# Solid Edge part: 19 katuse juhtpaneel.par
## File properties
Author: Henri
Template: Normal.par
Last saved by: Henri
Revision: 8
Application: Solid Edge
Accuracy: 0,990
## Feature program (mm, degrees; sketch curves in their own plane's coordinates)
sketch for "unnamed Protrusion 1" plane through (0, 0, 0) normal (0, 0, 1) x-axis (1, 0, 0)
  line (-20, -175) -> (-20, 175)
  line (-20, 175) -> (20, 175)
  line (20, 175) -> (20, -175)
  line (20, -175) -> (-20, -175)
extrude "unnamed Protrusion 1" add finite 40 along +normal
sketch for "ExtrudedProtrusion_2" plane through (0, 0, 0) normal (0, 0, 1) x-axis (1, 0, 0)
  line (-95, 62.5) -> (-20, 62.5)
  line (-20, 62.5) -> (-20, 112.5)
  line (-20, 112.5) -> (-95, 112.5)
  line (-95, 112.5) -> (-95, 62.5)
extrude "ExtrudedProtrusion_2" add finite 2.5 along +normal
sketch for "ExtrudedProtrusion_3" plane through (0, 0, 0) normal (0, 0, 1) x-axis (1, 0, 0)
  line (-35, 77.5) -> (-15, 77.5)
  line (-15, 97.5) -> (-15, 77.5)
  line (-35, 97.5) -> (-15, 97.5)
  line (-35, 97.5) -> (-35, 77.5)
extrude "ExtrudedProtrusion_3" add finite 60 along +normal
sketch for "ExtrudedProtrusion_4" plane through (-35, 87.5, 31.25) normal (-1, 0, 0) x-axis (0, -1, 0)
  circle centre (0, 21.25) radius 2.5
extrude "ExtrudedProtrusion_4" add finite 7.5 along +normal
sketch for "unnamed RevolvedProtrusion 1" plane through (-27.5, 87.5, 52.5) normal (0, 0, 1) x-axis (1, 0, 0)
  line (-14.5, 24) -> (-14.5, 18.25)
  line (-15, 17.75) -> (-14.5, 18.25)
  line (-15, 17.75) -> (-15, 14.75)
  line (-15, 14.75) -> (-14.5, 13.5427)
  line (-14.5, 13.5427) -> (-14.5, 0)
  line (-13.75, 0) -> (-14.5, 0)
  line (-13.75, 26.25) -> (-13.75, 0)
revolve "unnamed RevolvedProtrusion 1" add finite 360 deg
sketch for "unnamed RevolvedProtrusion 2" plane through (-27.5, 87.5, 52.5) normal (0, 0, 1) x-axis (1, 0, 0)
  circle centre (-13.75, 16.25) radius 1
revolve "unnamed RevolvedProtrusion 2" add finite 360 deg
pattern "Pattern_1" of "unnamed RevolvedProtrusion 1" along a curve  XDirCount = 9; XDirSpacing = 50 mm
revolve "unnamed RevolvedProtrusion 3" add finite 360 deg
revolve "unnamed RevolvedProtrusion 4" add finite 360 deg
revolve "unnamed RevolvedProtrusion 5" add finite 360 deg
revolve "unnamed RevolvedProtrusion 6" add finite 360 deg
revolve "unnamed RevolvedProtrusion 7" add finite 360 deg
revolve "unnamed RevolvedProtrusion 8" add finite 360 deg
revolve "unnamed RevolvedProtrusion 9" add finite 360 deg
revolve "unnamed RevolvedProtrusion 10" add finite 360 deg
fillet "Round_1" radius 1.5
sketch used by "ExtrudedProtrusion_6" plane through (0.75, 0, 40) normal (0, 0, 1) x-axis (0, 1, 0)
extrude "ExtrudedProtrusion_6" add finite 7.5 along +normal
sketch used by "unnamed Cutout 1" plane through (-0.6086, 106.7159, 43.75) normal (0.371391, -0.928477, 0) x-axis (0.928477, 0.371391, 0)
extrude "unnamed Cutout 1" cut through along -normal
sketch used by "unnamed Cutout 2" plane through (-8.0348, 49.7139, 43.75) normal (-0.371391, -0.928477, 0) x-axis (0.928477, -0.371391, 0)
extrude "unnamed Cutout 2" cut through along -normal
sketch for "unnamed Cutout 3" plane through (-4.3225, 116.0007, 44.7494) normal (-0.319569, -0.127827, 0.938901) x-axis (0.871748, 0.348699, 0.344186)
extrude "unnamed Cutout 3" cut finite 0.5 along -normal
sketch for "ExtrudedProtrusion_7" #1 plane through (-4.3225, 116.0007, 44.7494) normal (-0.319569, -0.127827, 0.938901) x-axis (0.871748, 0.348699, 0.344186)
  line (-6.7381, 8.75) -> (6.7381, 8.75)
  line (6.7381, 8.75) -> (6.7381, -8.75)
  line (-6.7381, -8.75) -> (6.7381, -8.75)
  line (-6.7381, 8.75) -> (-6.7381, -8.75)
sketch for "ExtrudedProtrusion_7" #2 plane through (-4.3225, 116.0007, 44.7494) normal (-0.319569, -0.127827, 0.938901) x-axis (0.871748, 0.348699, 0.344186)
sketch for "ExtrudedProtrusion_7" #3 plane through (-4.3225, 116.0007, 44.7494) normal (-0.319569, -0.127827, 0.938901) x-axis (0.871748, 0.348699, 0.344186)
  circle centre (-7.4881, 7.6034) radius 0.25
sketch for "ExtrudedProtrusion_7" #4 plane through (-4.3225, 116.0007, 44.7494) normal (-0.319569, -0.127827, 0.938901) x-axis (0.871748, 0.348699, 0.344186)
  circle centre (-7.4881, 6.7282) radius 0.25
sketch for "ExtrudedProtrusion_7" #5 plane through (-4.3225, 116.0007, 44.7494) normal (-0.319569, -0.127827, 0.938901) x-axis (0.871748, 0.348699, 0.344186)
  circle centre (-7.4881, 5.9624) radius 0.25
sketch for "ExtrudedProtrusion_7" #6 plane through (-4.3225, 116.0007, 44.7494) normal (-0.319569, -0.127827, 0.938901) x-axis (0.871748, 0.348699, 0.344186)
  circle centre (-7.4881, 4.4308) radius 0.25
sketch for "ExtrudedProtrusion_7" #7 plane through (-4.3225, 116.0007, 44.7494) normal (-0.319569, -0.127827, 0.938901) x-axis (0.871748, 0.348699, 0.344186)
  circle centre (-7.4881, 3.7014) radius 0.25
extrude "ExtrudedProtrusion_7" add finite 0.5 along +normal
fillet "Round_2" radius 0.2
sketch for "ExtrudedCutout_4" plane through (-4.3209, 58.9987, 44.75) normal (-0.319565, 0.127826, 0.938903) x-axis (0.871749, -0.3487, 0.344182)
extrude "ExtrudedCutout_4" cut finite 0.5 along -normal
sketch for "ExtrudedProtrusion_8" #1 plane through (-4.3209, 58.9987, 44.75) normal (-0.319565, 0.127826, 0.938903) x-axis (0.871749, -0.3487, 0.344182)
sketch for "ExtrudedProtrusion_8" #2 plane through (-4.3209, 58.9987, 44.75) normal (-0.319565, 0.127826, 0.938903) x-axis (0.871749, -0.3487, 0.344182)
  circle centre (-7.3671, -2.1335) radius 0.25
sketch for "ExtrudedProtrusion_8" #3 plane through (-4.3209, 58.9987, 44.75) normal (-0.319565, 0.127826, 0.938903) x-axis (0.871749, -0.3487, 0.344182)
  circle centre (-7.3671, -1.3677) radius 0.25
sketch for "ExtrudedProtrusion_8" #4 plane through (-4.3209, 58.9987, 44.75) normal (-0.319565, 0.127826, 0.938903) x-axis (0.871749, -0.3487, 0.344182)
  circle centre (-7.3671, 7.203) radius 0.25
extrude "ExtrudedProtrusion_8" add finite 0.5 along +normal
fillet "Round_3" radius 0.2
sketch used by "ExtrudedProtrusion_9" plane through (0, 87.5, 0) normal (0, -1, 0) x-axis (1, 0, 0)
  line (-57.5, 37.5) -> (-73.3744, 37.5)
  line (-55, 35) -> (-55, 30)
  line (-85, 27.5) -> (-57.5, 27.5)
  arc centre (-85, 32.5) radius 5 from (-90, 32.5) to (-85, 27.5) ccw
  arc centre (-57.5, 35) radius 2.5 from (-57.5, 37.5) to (-55, 35) cw
  arc centre (-57.5, 30) radius 2.5 from (-57.5, 27.5) to (-55, 30) ccw
  line (-90, 32.5) -> (-99.1666, 68.1143)
  line (-96.7455, 71.2375) -> (-91.5997, 71.2375)
  line (-89.3147, 69.7516) -> (-75.6595, 38.9858)
  arc centre (-96.7455, 68.7375) radius 2.5 from (-99.1666, 68.1143) to (-96.7455, 71.2375) cw
  arc centre (-91.5997, 68.7375) radius 2.5 from (-91.5997, 71.2375) to (-89.3147, 69.7516) cw
  arc centre (-73.3744, 40) radius 2.5 from (-75.6595, 38.9858) to (-73.3744, 37.5) ccw
extrude "ExtrudedProtrusion_9" add finite 35 symmetric
sketch for "unnamed Protrusion 2" plane through (0, 87.5, 0) normal (0, -1, 0) x-axis (1, 0, 0)
  line (-48.5, 12.5) -> (-35, 12.5)
  line (-35, 12.5) -> (-35, 7.5)
  line (-35, 7.5) -> (-48.5, 7.5)
  arc centre (-48.5, 9) radius 1.5 from (-50, 9) to (-48.5, 7.5) ccw
  line (-50, 11) -> (-50, 9)
  arc centre (-48.5, 11) radius 1.5 from (-50, 11) to (-48.5, 12.5) cw
extrude "unnamed Protrusion 2" add finite 30 symmetric
sketch for "unnamed RevolvedProtrusion 11" plane through (0, 87.5, 0) normal (0, -1, 0) x-axis (1, 0, 0)
revolve "unnamed RevolvedProtrusion 11" add finite 360 deg
fillet "Round_6" radius 2
sketch for "ExtrudedCutout_7" plane through (0, 87.5, 0) normal (0, -1, 0) x-axis (1, 0, 0)
  line (-89.3147, 69.7516) -> (-75.6595, 38.9858)
  arc centre (-73.3744, 40) radius 2.5 from (-75.6595, 38.9858) to (-73.3744, 37.5) ccw
  line (-73.3744, 37.5) -> (-57.5, 37.5)
  line (-57.5, 37.5) -> (-73.3744, 35)
  arc centre (-73.3744, 40) radius 5 from (-77.9445, 37.9716) to (-73.3744, 35) ccw
  line (-92.7093, 71.2375) -> (-77.9445, 37.9716)
  line (-92.7093, 71.2375) -> (-91.5997, 71.2375)
  arc centre (-91.5997, 68.7375) radius 2.5 from (-91.5997, 71.2375) to (-89.3147, 69.7516) cw
extrude "ExtrudedCutout_7" cut finite 25 symmetric
fillet "Round_7" radius 2.5
fillet "Round_8" radius 1
fillet "Round_10" radius 2
sketch for "unnamed Cutout 4" plane through (0.75, 0, 40) normal (0, 0, 1) x-axis (0, 1, 0)
  line (-175, -19.25) -> (0, -19.25)
  line (0, 21.0459) -> (0, -19.25)
  line (-175, 21.0459) -> (0, 21.0459)
  line (-175, 21.0459) -> (-175, -19.25)
extrude "unnamed Cutout 4" cut through along -normal
sketch for "ExtrudedProtrusion_13" plane through (0, 87.5, 0) normal (0, -1, 0) x-axis (1, 0, 0)
  line (-33.5, 60) -> (-16.5, 60)
  line (-33.5, 70) -> (-16.5, 60)
  line (-33.5, 70) -> (-33.5, 60)
extrude "ExtrudedProtrusion_13" add finite 17 symmetric
sketch for "ExtrudedCutout_10" plane through (-33.5, 87.5, 65) normal (-1, 0, 0) x-axis (0, -1, 0)
  line (7.75, 4.25) -> (-7.75, 4.25)
  line (-7.75, -4.25) -> (-7.75, 4.25)
  line (7.75, -4.25) -> (-7.75, -4.25)
  line (7.75, 4.25) -> (7.75, -4.25)
extrude "ExtrudedCutout_10" cut finite 0.25 along -normal
fillet "Round_11" radius 0.25
sketch for "ExtrudedCutout_11" plane through (0.75, 87.5, 40) normal (0, 0, 1) x-axis (0, 1, 0)
  line (87.5, -19.25) -> (-87.5, -19.25)
  line (-87.5, 20.75) -> (-87.5, -19.25)
  line (-87.5, 20.75) -> (-25, 20.75)
  line (-25, 13.25) -> (-25, 20.75)
  line (-25, 13.25) -> (25, 13.25)
  line (25, 20.75) -> (25, 13.25)
  line (25, 20.75) -> (87.5, 20.75)
  line (87.5, 20.75) -> (87.5, -19.25)
extrude "ExtrudedCutout_11" cut finite 25 along +normal  FiniteDepth2 = 50 mm
fillet "Round_12" radius 1.5
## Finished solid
Body 1: solid body, 228 faces, 427 edges, 194 vertices.
  Faces by surface: cylinder 103, plane 47, sphere 28, torus 24, cone 20, blend 6
  Edges by curve: line 180, circle 176, intersection 45, ellipse 26
Bounding box of the edges (mm; curved faces can reach further): 86.746 x 50.000 x 76.266, from (-99.2455, 62.5, 0) to (-12.5, 112.5, 76.2657).
Cylindrical faces by radius (mm): R0.25 x5, R0.75 x18, R1 x7, R1.25 x9, R1.5 x28, R2 x11, R2.5 x22, R5 x2, R10 x1
Conical faces (half-angle, radius in mm at the cone's reference point): 22.4965 deg R1.25 x9, 45 deg R0.75 x9, 45 deg R2.5 x1, 45 deg R7.5 x1
Toroidal faces (ring radius, tube radius in mm): R1.5 r1 x2, R2.5 r2.5 x2, R3 r1.5 x6, R3.5 r1 x2, R5 r2.5 x2, R8.5 r1.5 x1, R16.25 r1 x9
Spherical faces by radius (mm): R0.25 x2, R1.25 x9, R1.5 x8, R2.5 x8, R3.75 x1
Planar faces by outward normal: +x 5, +y 7, +z 9, -x 9, -y 7, -z 4, oblique 6
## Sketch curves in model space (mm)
line (-33.5, 79.75, 69.25) -> (-33.5, 95.25, 69.25)
line (-33.5, 79.75, 69.25) -> (-33.5, 79.75, 60.75)
line (-33.5, 79.75, 60.75) -> (-33.5, 95.25, 60.75)
line (-33.5, 95.25, 60.75) -> (-33.5, 95.25, 69.25)
line (20, -175, 40) -> (20, 0, 40)
line (-20.2959, -175, 40) -> (20, -175, 40)
line (-20.2959, -175, 40) -> (-20.2959, 0, 40)
line (-20.2959, 0, 40) -> (20, 0, 40)
arc centre (-73.3744, 87.5, 40) radius 5 from (-77.9445, 87.5, 37.9716) through (-76.1, 87.5, 35.8082) to (-73.3744, 87.5, 35)
line (-57.5, 87.5, 37.5) -> (-73.3744, 87.5, 35)
line (-73.3744, 87.5, 37.5) -> (-57.5, 87.5, 37.5)
arc centre (-73.3744, 87.5, 40) radius 2.5 from (-75.6595, 87.5, 38.9858) through (-74.7372, 87.5, 37.9041) to (-73.3744, 87.5, 37.5)
line (-89.3147, 87.5, 69.7516) -> (-75.6595, 87.5, 38.9858)
arc centre (-91.5997, 87.5, 68.7375) radius 2.5 from (-91.5997, 87.5, 71.2375) through (-90.2369, 87.5, 70.8333) to (-89.3147, 87.5, 69.7516)
line (-92.7093, 87.5, 71.2375) -> (-91.5997, 87.5, 71.2375)
line (-92.7093, 87.5, 71.2375) -> (-77.9445, 87.5, 37.9716)
circle centre (-44, 87.5, 52.5) radius 16.25
arc centre (-73.3744, 87.5, 40) radius 2.5 from (-75.6595, 87.5, 38.9858) through (-74.7372, 87.5, 37.9041) to (-73.3744, 87.5, 37.5)
line (-89.3147, 87.5, 69.7516) -> (-75.6595, 87.5, 38.9858)
arc centre (-91.5997, 87.5, 68.7375) radius 2.5 from (-91.5997, 87.5, 71.2375) through (-90.2369, 87.5, 70.8333) to (-89.3147, 87.5, 69.7516)
line (-96.7455, 87.5, 71.2375) -> (-91.5997, 87.5, 71.2375)
arc centre (-96.7455, 87.5, 68.7375) radius 2.5 from (-99.1666, 87.5, 68.1143) through (-98.6755, 87.5, 70.3266) to (-96.7455, 87.5, 71.2375)
line (-90, 87.5, 32.5) -> (-99.1666, 87.5, 68.1143)
arc centre (-85, 87.5, 32.5) radius 5 from (-90, 87.5, 32.5) through (-88.4312, 87.5, 28.8631) to (-85, 87.5, 27.5)
line (-85, 87.5, 27.5) -> (-57.5, 87.5, 27.5)
arc centre (-57.5, 87.5, 30) radius 2.5 from (-57.5, 87.5, 27.5) through (-55.6816, 87.5, 28.2844) to (-55, 87.5, 30)
line (-55, 87.5, 35) -> (-55, 87.5, 30)
arc centre (-57.5, 87.5, 35) radius 2.5 from (-57.5, 87.5, 37.5) through (-55.6816, 87.5, 36.7156) to (-55, 87.5, 35)
line (-57.5, 87.5, 37.5) -> (-73.3744, 87.5, 37.5)
circle centre (-41.25, 103.75, 52.5) radius 1
line (-42.4017, 87.5, 52.5) -> (-39.1797, 87.5, 52.5)
line (-7.5722, 103.9305, 47.5) -> (6.3581, 109.5026, 47.5)
line (-7.5722, 103.9305, 47.5) -> (-7.5722, 103.9305, 42)
line (-7.5722, 103.9305, 42) -> (6.3581, 109.5026, 47.5)
line (-15, 52.5, 42) -> (-1.0695, 46.9278, 47.5)
line (-15, 52.5, 47.5) -> (-15, 52.5, 42)
line (-15, 52.5, 47.5) -> (-1.0695, 46.9278, 47.5)
arc centre (-48.5, 87.5, 9) radius 1.5 from (-50, 87.5, 9) through (-49.5294, 87.5, 7.9089) to (-48.5, 87.5, 7.5)
line (-50, 87.5, 11) -> (-50, 87.5, 9)
arc centre (-48.5, 87.5, 11) radius 1.5 from (-50, 87.5, 11) through (-49.5294, 87.5, 12.0911) to (-48.5, 87.5, 12.5)
line (-48.5, 87.5, 12.5) -> (-35, 87.5, 12.5)
line (-35, 87.5, 12.5) -> (-35, 87.5, 7.5)
line (-35, 87.5, 7.5) -> (-48.5, 87.5, 7.5)
arc centre (-75, 87.5, 17.5) radius 3.75 from (-77.5, 87.5, 14.7049) through (-78.7484, 87.5, 17.6087) to (-77.5, 87.5, 20.2951)
arc centre (-75, 87.5, 17.5) radius 3.75 from (-77.5, 87.5, 14.7049) through (-78.7484, 87.5, 17.6087) to (-77.5, 87.5, 20.2951)
line (-77.5, 87.5, 12.5) -> (-77.5, 87.5, 14.7049)
line (-77.5, 87.5, 12.5) -> (-82.5, 87.5, 7.5)
line (-83.5, 87.5, 7.5) -> (-82.5, 87.5, 7.5)
arc centre (-83.5, 87.5, 6) radius 1.5 from (-85, 87.5, 6) through (-84.5294, 87.5, 7.0911) to (-83.5, 87.5, 7.5)
line (-85, 87.5, 2.5) -> (-85, 87.5, 6)
line (-75, 87.5, 2.5) -> (-85, 87.5, 2.5)
line (-77.5, 87.5, 20.2951) -> (-77.5, 87.5, 22.5)
line (-82.5, 87.5, 27.5) -> (-77.5, 87.5, 22.5)
line (-75, 87.5, 27.5) -> (-82.5, 87.5, 27.5)
line (-75, 87.5, 27.5) -> (-75, 87.5, 2.5)
circle centre (-11.954, 116.1491, 42.1721) radius 0.25
circle centre (-12.2249, 116.8263, 42.1721) radius 0.25
circle centre (-12.4958, 117.5035, 42.1721) radius 0.25
circle centre (-13.0646, 118.9255, 42.1721) radius 0.25
circle centre (-13.349, 119.6366, 42.1721) radius 0.25
circle centre (-13.9449, 121.1264, 42.1721) radius 0.25
circle centre (-13.6741, 120.4492, 42.1721) radius 0.25
line (-6.9467, 105.5269, 42.4302) -> (4.801, 110.226, 47.0685)
line (-1.6983, 126.4744, 47.0685) -> (4.801, 110.226, 47.0685)
line (-13.4461, 121.7753, 42.4302) -> (-1.6983, 126.4744, 47.0685)
line (-13.4461, 121.7753, 42.4302) -> (-6.9467, 105.5269, 42.4302)
circle centre (-11.5355, 59.5866, 42.2144) radius 0.25
circle centre (-11.251, 60.2977, 42.2144) radius 0.25
circle centre (-8.068, 68.2553, 42.2144) radius 0.25
circle centre (-7.7294, 69.1019, 42.2144) radius 0.25
line (4.8044, 64.7726, 47.0698) -> (-1.695, 48.5243, 47.0698)
line (-1.695, 48.5243, 47.0698) -> (-13.4461, 53.2247, 42.4302)
line (-6.9467, 69.4731, 42.4302) -> (-13.4461, 53.2247, 42.4302)
line (-6.9467, 69.4731, 42.4302) -> (4.8044, 64.7726, 47.0698)
line (-33.5, 87.5, 60) -> (-16.5, 87.5, 60)
line (-33.5, 87.5, 70) -> (-16.5, 87.5, 60)
line (-33.5, 87.5, 70) -> (-33.5, 87.5, 60)
line (-42.5, 105.25, 52.5) -> (-42, 105.75, 52.5)
line (-42.5, 105.25, 52.5) -> (-42.5, 102.25, 52.5)
line (-42.5, 102.25, 52.5) -> (-42, 101.0427, 52.5)
line (-42, 101.0427, 52.5) -> (-42, 87.5, 52.5)
line (-41.25, 87.5, 52.5) -> (-42, 87.5, 52.5)
line (-41.25, 113.75, 52.5) -> (-41.25, 87.5, 52.5)
arc centre (-41.25, 112.5, 52.5) radius 1.25 from (-42, 111.5, 52.5) through (-42.4359, 112.8953, 52.5) to (-41.25, 113.75, 52.5)
line (-42, 111.5, 52.5) -> (-42, 105.75, 52.5)
circle centre (-42.5, 87.5, 52.5) radius 16.25
line (-35, 87.5, 52.5) -> (-45, 87.5, 52.5)
circle centre (-35, 87.5, 52.5) radius 2.5
line (-35, 87.5, 64.2069) -> (-35, 87.5, 43.5789)
line (-35, 69.5584, 52.5) -> (-35, 104.2903, 52.5)
line (-23.8304, 122.5, 40) -> (26.1084, 122.5, 40)
line (-25.2462, 52.5, 40) -> (23.9204, 52.5, 40)
line (-10, 97.5, 40) -> (8.218, 97.5, 40)
line (-10, 77.5, 40) -> (3.8419, 77.5, 40)
line (-14.5634, 62.5, 40) -> (8.3467, 62.5, 40)
line (-13.405, 112.5, 40) -> (13.6237, 112.5, 40)
line (-10, 58.4341, 40) -> (-10, 115.8381, 40)
line (-5, 41.5733, 40) -> (-5, 127.4218, 40)
line (-15, 48.6523, 40) -> (-15, 126.2635, 40)
line (-32.5, 95, 40) -> (-17.5, 95, 40)
line (-17.5, 95, 40) -> (-17.5, 80, 40)
line (-17.5, 80, 40) -> (-32.5, 80, 40)
line (-32.5, 80, 40) -> (-32.5, 95, 40)
line (-7.5722, 71.0695, 40) -> (6.3583, 65.4973, 40)
line (6.3583, 65.4973, 40) -> (-1.0695, 46.9278, 40)
line (-1.0695, 46.9278, 40) -> (-15, 52.5, 40)
line (-15, 52.5, 40) -> (-7.5722, 71.0695, 40)
line (-7.5722, 103.9305, 40) -> (6.355, 109.5013, 40)
line (6.355, 109.5013, 40) -> (-1.0728, 128.0709, 40)
line (-1.0728, 128.0709, 40) -> (-15, 122.5, 40)
line (-15, 122.5, 40) -> (-7.5722, 103.9305, 40)
line (-10.7842, 99.1914, 0) -> (-10.7842, 73.4747, 0)
line (-129.3743, 87.5, 0) -> (-45.0579, 87.5, 0)
line (-15, 97.5, 0) -> (-15, 77.5, 0)
line (-35, 77.5, 0) -> (-15, 77.5, 0)
line (-35, 97.5, 0) -> (-35, 77.5, 0)
line (-35, 97.5, 0) -> (-15, 97.5, 0)
line (-95, 112.5, 0) -> (-95, 62.5, 0)
line (-95, 62.5, 0) -> (-20, 62.5, 0)
line (-20, 62.5, 0) -> (-20, 112.5, 0)
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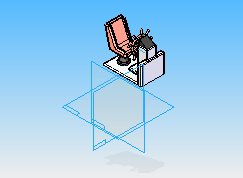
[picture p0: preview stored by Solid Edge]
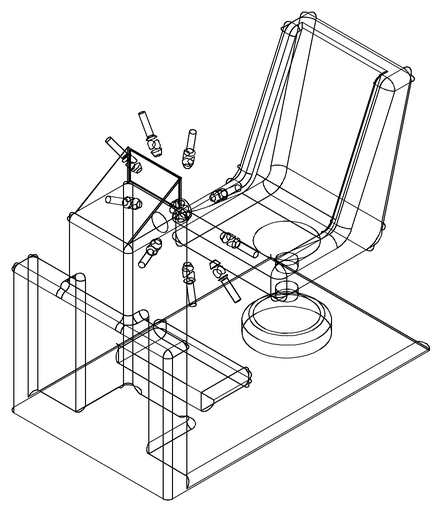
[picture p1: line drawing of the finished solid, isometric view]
